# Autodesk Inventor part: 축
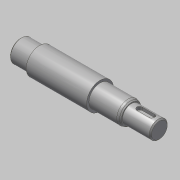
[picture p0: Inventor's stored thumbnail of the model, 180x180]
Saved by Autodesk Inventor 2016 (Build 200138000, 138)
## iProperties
Created: 2016-06
Part Number: 축
Material: 강철, 연강
Document SubType Name: Modeling
Designer: mduedu
Density: 7.86 g/cm^3
Appearance: 강철
Author: mduedu
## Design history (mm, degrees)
sketch "스케치1"
  geometry: L1 (-62, 0)-(62, 0); L2 (-62, 0)-(-62, 10); L3 (-62, 10)-(-45, 10); L4 (-45, 10)-(-45, 12); L5 (-45, 12)-(9, 12); L6 (9, 12)-(9, 10); L7 (9, 10)-(37, 10); L8 (37, 10)-(37, 8); L9 (37, 8)-(62, 8); L10 (62, 8)-(62, 0); 2 further points
  constraints: 20 end point, 5 parallel, 2 perpendicular, 1 coincident, 1 collinear, 1 horizontal, 1 midpoint, 1 vertical
  dimensions: "d0" = 124 distance of L1.start L1.end; "d2" = 16 diameter of L9 L1; "d3" = 20 diameter of L7 L1; "d4" = 24 diameter of L5 L1; "d5" = 20 diameter of L3 L1; "d6" = 17 distance of L2.end L3.end; "d7" = 25 distance of L8.end L9.end; "d8" = 53 distance from line of L5.end L10
revolve "회전1" sketch "스케치1" stored, may be unused: angle "d9" = 90 deg
chamfer "모따기1" distance "d10" = 2; stored, may be unused: second distance "d11" = 2, angle "d12" = 30 deg
fillet "모깎기1" dims "d13" = 4
node "작업 평면1"
sketch "스케치2"
  geometry: L1 (-5, 2.5)-(6, 2.5); L2 (6, -2.5)-(-5, -2.5); L3 (-5, 0)-(6, 0); L4 (-12.5, 8.845)-(-12.5, -8.845) reference; A1 r 2.5 centre (-5, 0) between (-5, 2.5) and (-5, -2.5); A2 r 2.5 centre (6, 0) between (6, -2.5) and (6, 2.5); 1 further point
  constraints: 6 end point, 4 point on circle, 3 tangent, 2 centre point, 2 parallel, 1 horizontal, 1 horizontal alignment
  dimensions: "d14" = 5 distance edge to line of A1 L4; "d15" = 5 distance between parallel lines of L2 L1; "d16" = 16 dimension on A2 A1
extrude "돌출1" cut sketch "스케치2" distance "d17" = 3; taper "d18" = 0 deg
chamfer "모따기2" distance "d19" = 1; stored, may be unused: second distance "d20" = 2, angle "d21" = 30 deg
sketch "스케치3"
  geometry: L1 (-37, -8)-(-61, -8) reference; L2 (-62, -7)-(-62, 7) reference; L3 (-38.5, -8)-(-40, -6.5); L4 (-40, -6.5)-(-40, -8); L5 (-38.5, -8)-(-40, -8); 1 further point
  constraints: 6 end point, 2 point on line, 1 collinear, 1 vertical
  dimensions: "d22" = 45 deg angle of L4 L3; "d23" = 22 distance between parallel lines of L2 L4; "d24" = 3 diameter of L3.start L4
revolve "회전2" stored, may be unused: angle "d25" = 90 deg
node "작업점1"
sketch "스케치4"
  geometry: 1 further point
hole "구멍1" sketch "스케치4" at (0, 0) diameter "d26" = 3.242; stored, may be unused: countersink angle "d30" = 90 deg, drill point angle "d32" = 120 deg; dims "d27" = 8, "d28" = 4, "d29" = 2, "d31" = 11
chamfer "모따기3" distance "d33" = 2; stored, may be unused: second distance "d34" = 2, angle "d35" = 30 deg
node "솔리드1"
